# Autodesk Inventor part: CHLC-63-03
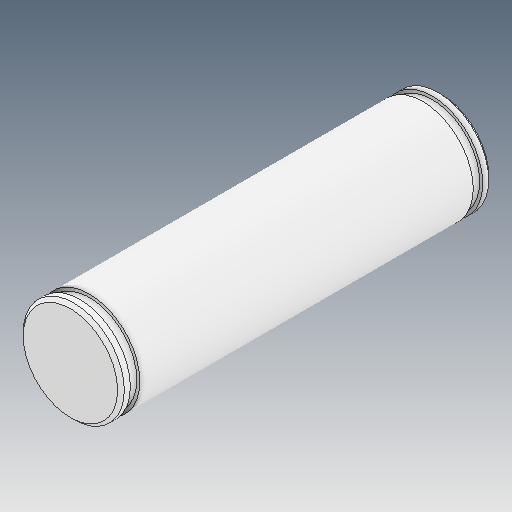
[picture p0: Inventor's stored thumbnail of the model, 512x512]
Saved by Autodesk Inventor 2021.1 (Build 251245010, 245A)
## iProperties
Created: 2021-05
Part Number: CHLC-63-03
Material: Ogólny
Document SubType Name: Modeling
Designer: user
Density: 1 g/cm^3
Appearance: Domyślna
Author: user
Revision Number: ÈÎºÎ
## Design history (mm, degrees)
feature "ÊäÈë1"
node "Bryła1"
